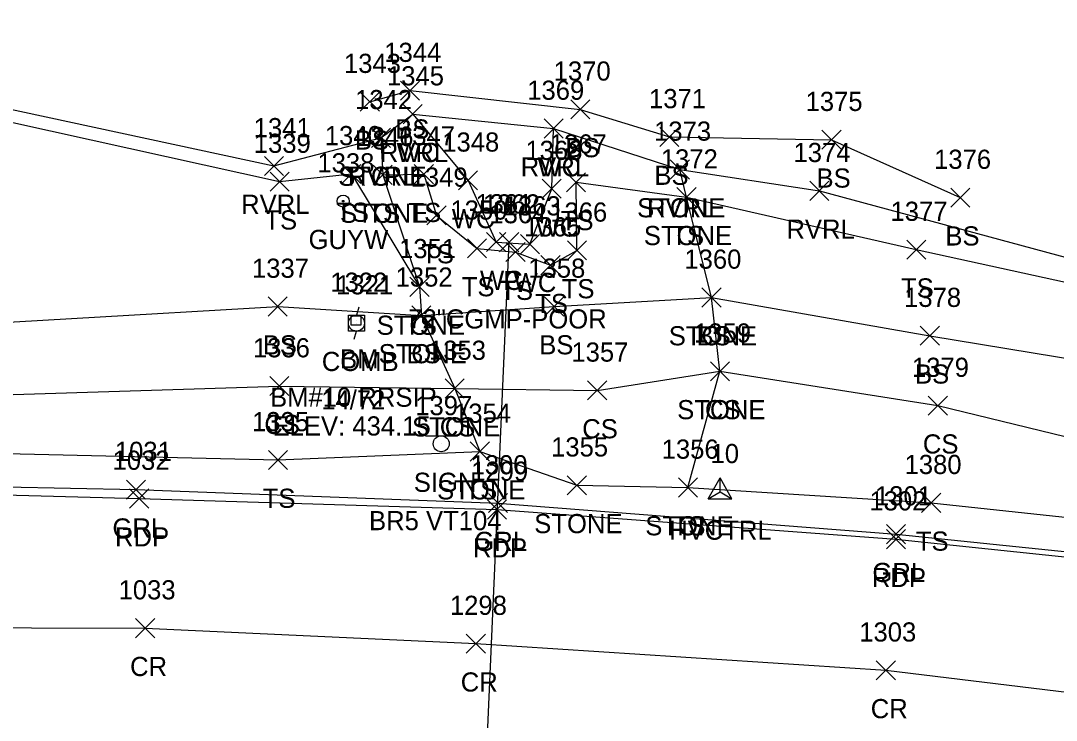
# Model space of a CAD drawing. Extents: x 1514253 to 1516033, y 782541 to 785002.
# Drawn here: x 1515259.8 to 1515367.9, y 782689.3 to 782762.3 of the extents above; entities that cross this region are included whole.
import ezdxf

# ---------------------------------------------------------------- set-up
doc = ezdxf.new("R2010")
doc.units = 0
for name, color, linetype in [('C_A', 7, 'Continuous'), ('C_C', 7, 'Continuous'), ('C_I', 7, 'Continuous'), ('CPBM', 7, 'Continuous'), ('CPSM', 7, 'Continuous'), ('D_A', 7, 'Continuous'), ('D_C', 7, 'Continuous'), ('D_I', 7, 'Continuous'), ('D_TIC', 7, 'Continuous'), ('DCP', 7, 'Continuous'), ('L_A', 7, 'Continuous'), ('L_I', 7, 'Continuous'), ('L_TIC', 7, 'Continuous'), ('LASF', 7, 'Continuous'), ('LAWE', 7, 'Continuous'), ('LELB', 7, 'Continuous'), ('P_A', 7, 'Continuous'), ('P_I', 7, 'Continuous'), ('P_TIC', 7, 'Continuous'), ('PET', 7, 'Continuous'), ('PRC', 7, 'Continuous'), ('R_A', 7, 'Continuous'), ('R_I', 7, 'Continuous'), ('R_TIC', 7, 'Continuous'), ('RGR', 7, 'Continuous'), ('S_A', 7, 'Continuous'), ('S_C', 7, 'Continuous'), ('S_I', 7, 'Continuous'), ('SSGN', 7, 'Continuous'), ('U_A', 7, 'Continuous'), ('U_C', 7, 'Continuous'), ('U_I', 7, 'Continuous'), ('UP', 7, 'Continuous'), ('UPGW', 7, 'Continuous')]:
    doc.layers.add(name, color=color, linetype=linetype)

msp = doc.modelspace()

# ---------------------------------------------------------------- linework, layer by layer
at = {"layer": 'CPBM'}
for p, q in [((1515294.35, 782730.48), (1515294.35, 782731.48)), ((1515294.35, 782731.48), (1515295.35, 782731.48)), ((1515295.35, 782731.48), (1515295.35, 782730.48)), ((1515295.35, 782730.48), (1515294.35, 782730.48)), ((1515294.85, 782730.98), (1515294.85, 782730.98)), ((1515294.85, 782730.98), (1515294.85, 782730.98))]:
    msp.add_line(p, q, dxfattribs=at)
at = {"layer": 'CPSM'}
for p, q in [((1515331.58, 782712.38), (1515332.83, 782714.55)), ((1515334.08, 782712.38), (1515332.83, 782714.55)), ((1515332.83, 782713.1), (1515332.83, 782714.55)), ((1515331.58, 782712.38), (1515332.83, 782713.1)), ((1515332.83, 782713.1), (1515332.83, 782713.1)), ((1515332.83, 782713.1), (1515334.08, 782712.38)), ((1515331.58, 782712.38), (1515334.08, 782712.38))]:
    msp.add_line(p, q, dxfattribs=at)
at = {"layer": 'D_TIC'}
for points in [[(1515309.82, 782738.15), (1515311.82, 782740.15)], [(1515311.82, 782738.15), (1515309.82, 782740.15)]]:
    msp.add_lwpolyline(points, dxfattribs=at)
at = {"layer": 'DCP'}
msp.add_lwpolyline([(1515307.3, 782659.25), (1515310.82, 782739.15)], dxfattribs=at)
at = {"layer": 'L_TIC'}
for points in [[(1515299.48, 782753.97), (1515301.48, 782755.97)], [(1515301.48, 782753.97), (1515299.48, 782755.97)], [(1515295.28, 782752.82), (1515297.28, 782754.82)], [(1515297.28, 782752.82), (1515295.28, 782754.82)], [(1515299.76, 782751.52), (1515301.76, 782753.52)], [(1515301.76, 782751.52), (1515299.76, 782753.52)], [(1515299.76, 782751.52), (1515301.76, 782753.52)], [(1515301.76, 782751.52), (1515299.76, 782753.52)], [(1515317.25, 782752.02), (1515319.25, 782754.02)], [(1515319.25, 782752.02), (1515317.25, 782754.02)], [(1515314.46, 782750.02), (1515316.46, 782752.02)], [(1515316.46, 782750.02), (1515314.46, 782752.02)], [(1515314.46, 782750.02), (1515316.46, 782752.02)], [(1515316.46, 782750.02), (1515314.46, 782752.02)], [(1515296.44, 782749.04), (1515298.44, 782751.04)], [(1515298.44, 782749.04), (1515296.44, 782751.04)], [(1515296.44, 782749.04), (1515298.44, 782751.04)], [(1515298.44, 782749.04), (1515296.44, 782751.04)], [(1515326.54, 782749.14), (1515328.54, 782751.14)], [(1515328.54, 782749.14), (1515326.54, 782751.14)], [(1515343.46, 782748.85), (1515345.46, 782750.85)], [(1515345.46, 782748.85), (1515343.46, 782750.85)], [(1515285.28, 782746.11), (1515287.28, 782748.11)], [(1515287.28, 782746.11), (1515285.28, 782748.11)], [(1515327.64, 782745.75), (1515329.64, 782747.75)], [(1515329.64, 782745.75), (1515327.64, 782747.75)], [(1515327.64, 782745.75), (1515329.64, 782747.75)], [(1515329.64, 782745.75), (1515327.64, 782747.75)], [(1515293.36, 782745.28), (1515295.36, 782747.28)], [(1515295.36, 782745.28), (1515293.36, 782747.28)], [(1515296.63, 782745.18), (1515298.63, 782747.18)], [(1515298.63, 782745.18), (1515296.63, 782747.18)], [(1515296.63, 782745.18), (1515298.63, 782747.18)], [(1515298.63, 782745.18), (1515296.63, 782747.18)], [(1515300.91, 782745.26), (1515302.91, 782747.26)], [(1515302.91, 782745.26), (1515300.91, 782747.26)], [(1515305.53, 782744.61), (1515307.53, 782746.61)], [(1515307.53, 782744.61), (1515305.53, 782746.61)], [(1515285.87, 782744.48), (1515287.87, 782746.48)], [(1515287.87, 782744.48), (1515285.87, 782746.48)], [(1515314.26, 782743.74), (1515316.26, 782745.74)], [(1515316.26, 782743.74), (1515314.26, 782745.74)], [(1515316.8, 782744.41), (1515318.8, 782746.41)], [(1515318.8, 782744.41), (1515316.8, 782746.41)], [(1515342.2, 782743.52), (1515344.2, 782745.52)], [(1515344.2, 782743.52), (1515342.2, 782745.52)], [(1515328.34, 782742.85), (1515330.34, 782744.85)], [(1515330.34, 782742.85), (1515328.34, 782744.85)], [(1515328.34, 782742.85), (1515330.34, 782744.85)], [(1515330.34, 782742.85), (1515328.34, 782744.85)], [(1515356.91, 782742.81), (1515358.91, 782744.81)], [(1515358.91, 782742.81), (1515356.91, 782744.81)], [(1515302.24, 782740.95), (1515304.24, 782742.95)], [(1515304.24, 782740.95), (1515302.24, 782742.95)], [(1515308.47, 782738.17), (1515310.47, 782740.17)], [(1515310.47, 782738.17), (1515308.47, 782740.17)], [(1515306.47, 782737.51), (1515308.47, 782739.51)], [(1515308.47, 782737.51), (1515306.47, 782739.51)], [(1515310.49, 782737.13), (1515312.49, 782739.13)], [(1515312.49, 782737.13), (1515310.49, 782739.13)], [(1515311.99, 782737.95), (1515313.99, 782739.95)], [(1515313.99, 782737.95), (1515311.99, 782739.95)], [(1515316.9, 782737.3), (1515318.9, 782739.3)], [(1515318.9, 782737.3), (1515316.9, 782739.3)], [(1515352.31, 782737.38), (1515354.31, 782739.38)], [(1515354.31, 782737.38), (1515352.31, 782739.38)], [(1515314.13, 782735.76), (1515316.13, 782737.76)], [(1515316.13, 782735.76), (1515314.13, 782737.76)], [(1515300.46, 782733.49), (1515302.46, 782735.49)], [(1515302.46, 782733.49), (1515300.46, 782735.49)], [(1515300.46, 782733.49), (1515302.46, 782735.49)], [(1515302.46, 782733.49), (1515300.46, 782735.49)], [(1515330.94, 782732.39), (1515332.94, 782734.39)], [(1515332.94, 782732.39), (1515330.94, 782734.39)], [(1515330.94, 782732.39), (1515332.94, 782734.39)], [(1515332.94, 782732.39), (1515330.94, 782734.39)], [(1515285.67, 782731.44), (1515287.67, 782733.44)], [(1515287.67, 782731.44), (1515285.67, 782733.44)], [(1515300.66, 782730.52), (1515302.66, 782732.52)], [(1515302.66, 782730.52), (1515300.66, 782732.52)], [(1515300.66, 782730.52), (1515302.66, 782732.52)], [(1515302.66, 782730.52), (1515300.66, 782732.52)], [(1515314.52, 782731.45), (1515316.52, 782733.45)], [(1515316.52, 782731.45), (1515314.52, 782733.45)], [(1515353.73, 782728.4), (1515355.73, 782730.4)], [(1515355.73, 782728.4), (1515353.73, 782730.4)], [(1515331.82, 782724.68), (1515333.82, 782726.68)], [(1515333.82, 782724.68), (1515331.82, 782726.68)], [(1515331.82, 782724.68), (1515333.82, 782726.68)], [(1515333.82, 782724.68), (1515331.82, 782726.68)], [(1515285.83, 782723.14), (1515287.83, 782725.14)], [(1515287.83, 782723.14), (1515285.83, 782725.14)], [(1515304.14, 782722.88), (1515306.14, 782724.88)], [(1515306.14, 782722.88), (1515304.14, 782724.88)], [(1515304.14, 782722.88), (1515306.14, 782724.88)], [(1515306.14, 782722.88), (1515304.14, 782724.88)], [(1515319.01, 782722.69), (1515321.01, 782724.69)], [(1515321.01, 782722.69), (1515319.01, 782724.69)], [(1515354.56, 782721.1), (1515356.56, 782723.1)], [(1515356.56, 782721.1), (1515354.56, 782723.1)], [(1515285.69, 782715.43), (1515287.69, 782717.43)], [(1515287.69, 782715.43), (1515285.69, 782717.43)], [(1515306.76, 782716.31), (1515308.76, 782718.31)], [(1515308.76, 782716.31), (1515306.76, 782718.31)], [(1515306.76, 782716.31), (1515308.76, 782718.31)], [(1515308.76, 782716.31), (1515306.76, 782718.31)], [(1515316.89, 782712.79), (1515318.89, 782714.79)], [(1515318.89, 782712.79), (1515316.89, 782714.79)], [(1515328.48, 782712.56), (1515330.48, 782714.56)], [(1515330.48, 782712.56), (1515328.48, 782714.56)], [(1515328.48, 782712.56), (1515330.48, 782714.56)], [(1515330.48, 782712.56), (1515328.48, 782714.56)], [(1515353.86, 782710.96), (1515355.86, 782712.96)], [(1515355.86, 782710.96), (1515353.86, 782712.96)]]:
    msp.add_lwpolyline(points, dxfattribs=at)
at = {"layer": 'LASF'}
msp.add_lwpolyline([(1515297.44, 782750.04), (1515297.63, 782746.18), (1515301.46, 782734.49), (1515301.66, 782731.52), (1515305.14, 782723.88), (1515307.76, 782717.31), (1515317.89, 782713.79), (1515329.48, 782713.56), (1515332.82, 782725.68), (1515331.94, 782733.39), (1515329.34, 782743.85), (1515328.64, 782746.75)], dxfattribs=at)
at = {"layer": 'LAWE'}
for points in [[(1515202.17, 782762.27), (1515243.71, 782756.27), (1515286.28, 782747.11), (1515297.44, 782750.04), (1515300.76, 782752.52), (1515315.46, 782751.02), (1515328.64, 782746.75), (1515343.2, 782744.52), (1515396.17, 782730.21), (1515410.48, 782726.67), (1515425.65, 782730.86), (1515462.57, 782730.18)], [(1515300.76, 782752.52), (1515306.53, 782745.61), (1515309.47, 782739.17), (1515312.99, 782738.95), (1515315.26, 782744.74), (1515315.46, 782751.02)]]:
    msp.add_lwpolyline(points, dxfattribs=at)
at = {"layer": 'LELB'}
for points in [[(1515202.79, 782759.81), (1515243.26, 782755.13), (1515286.87, 782745.48), (1515294.36, 782746.28), (1515301.46, 782734.49)], [(1515296.28, 782753.82), (1515300.48, 782754.97), (1515318.25, 782753.02), (1515327.54, 782750.14), (1515344.46, 782749.85), (1515357.91, 782743.81)], [(1515297.63, 782746.18), (1515301.91, 782746.26), (1515303.24, 782741.95), (1515307.47, 782738.51), (1515311.49, 782738.13), (1515315.13, 782736.76), (1515317.9, 782738.3), (1515317.8, 782745.41), (1515329.34, 782743.85), (1515353.31, 782738.38), (1515396.39, 782728.96), (1515412.77, 782722.27), (1515425.22, 782714.96)], [(1515201.95, 782733.37), (1515243.57, 782729.95), (1515286.67, 782732.44), (1515301.66, 782731.52), (1515315.52, 782732.45), (1515331.94, 782733.39), (1515354.73, 782729.4), (1515394.7, 782722.81), (1515412.77, 782722.27)], [(1515200.97, 782724.68), (1515243.49, 782722.77), (1515286.83, 782724.14), (1515305.14, 782723.88), (1515320.01, 782723.69), (1515332.82, 782725.68), (1515355.56, 782722.1), (1515394.29, 782712.68), (1515425.22, 782714.96), (1515459.54, 782709.6)], [(1515200.03, 782717.69), (1515243.31, 782717.45), (1515286.69, 782716.43), (1515307.76, 782717.31)], [(1515329.48, 782713.56), (1515354.86, 782711.96), (1515389.93, 782708.21), (1515422.77, 782703.93), (1515456.54, 782698.83)]]:
    msp.add_lwpolyline(points, dxfattribs=at)
at = {"layer": 'P_TIC'}
for points in [[(1515271.2, 782711.4), (1515273.2, 782713.4)], [(1515273.2, 782711.4), (1515271.2, 782713.4)], [(1515308.56, 782710.26), (1515310.56, 782712.26)], [(1515310.56, 782710.26), (1515308.56, 782712.26)], [(1515350.19, 782707.16), (1515352.19, 782709.16)], [(1515352.19, 782707.16), (1515350.19, 782709.16)], [(1515271.83, 782697.88), (1515273.83, 782699.88)], [(1515273.83, 782697.88), (1515271.83, 782699.88)], [(1515306.34, 782696.26), (1515308.34, 782698.26)], [(1515308.34, 782696.26), (1515306.34, 782698.26)], [(1515349.13, 782693.48), (1515351.13, 782695.48)], [(1515351.13, 782693.48), (1515349.13, 782695.48)]]:
    msp.add_lwpolyline(points, dxfattribs=at)
at = {"layer": 'PET'}
msp.add_lwpolyline([(1515198.6, 782712.94), (1515237.64, 782713.34), (1515272.2, 782712.4), (1515309.56, 782711.26), (1515351.19, 782708.16), (1515392.07, 782703.88), (1515423.17, 782699.74), (1515455.77, 782695.06)], dxfattribs=at)
at = {"layer": 'PRC'}
msp.add_lwpolyline([(1515198.29, 782698.44), (1515237.18, 782698.99), (1515272.83, 782698.88), (1515307.34, 782697.26), (1515350.13, 782694.48), (1515391.03, 782689.51), (1515420.87, 782685.75), (1515453.49, 782680.58)], dxfattribs=at)
at = {"layer": 'R_TIC'}
for points in [[(1515270.88, 782712.33), (1515272.88, 782714.33)], [(1515272.88, 782712.33), (1515270.88, 782714.33)], [(1515308.65, 782710.93), (1515310.65, 782712.93)], [(1515310.65, 782710.93), (1515308.65, 782712.93)], [(1515350.2, 782707.69), (1515352.2, 782709.69)], [(1515352.2, 782707.69), (1515350.2, 782709.69)]]:
    msp.add_lwpolyline(points, dxfattribs=at)
at = {"layer": 'RGR'}
msp.add_lwpolyline([(1515198.57, 782713.8), (1515237.6, 782714.04), (1515271.88, 782713.33), (1515309.65, 782711.93), (1515351.2, 782708.69), (1515392.07, 782704.46), (1515423.15, 782700.51), (1515456.3, 782695.76)], dxfattribs=at)
at = {"layer": 'SSGN'}
for p, q in [((1515302.08, 782718.95), (1515305.42, 782718.95)), ((1515303.73, 782718.12), (1515303.73, 782718.12))]:
    msp.add_line(p, q, dxfattribs=at)
msp.add_circle((1515303.73, 782718.12), 0.833, dxfattribs=at)
at = {"layer": 'UP'}
for p, q in [((1515294.05, 782729.88), (1515294.05, 782731.55)), ((1515294.05, 782731.55), (1515295.72, 782731.55)), ((1515295.13, 782732.38), (1515294.88, 782731.55)), ((1515295.72, 782731.55), (1515295.72, 782729.88)), ((1515294.88, 782730.71), (1515294.88, 782730.71)), ((1515295.72, 782729.88), (1515294.05, 782729.88)), ((1515294.63, 782729.05), (1515294.88, 782729.88))]:
    msp.add_line(p, q, dxfattribs=at)
msp.add_circle((1515294.88, 782730.71), 0.833, dxfattribs=at)
at = {"layer": 'UPGW'}
for radius in [0.625, 0.0833]:
    msp.add_circle((1515293.5, 782743.44), radius, dxfattribs=at)

# ---------------------------------------------------------------- texts
at = {"layer": 'C_A'}
for s, p in [('BM', (1515293.17, 782725.98)), ('HVCTRL', (1515327.52, 782708.1))]:
    msp.add_text(s, height=2, dxfattribs=at).set_placement(p)
at = {"layer": 'C_C'}
for s, p in [('BM#10 RRSIP', (1515285.87, 782721.98)), ('ELEV: 434.15', (1515286.13, 782718.98))]:
    msp.add_text(s, height=2, dxfattribs=at).set_placement(p)
at = {"layer": 'C_I'}
for s, p in [('1322', (1515292.16, 782733.98)), ('10', (1515331.84, 782716.1))]:
    msp.add_text(s, height=2, dxfattribs=at).set_placement(p)
at = {"layer": 'D_A'}
msp.add_text('P', height=2, dxfattribs=at).set_placement((1515310.2, 782734.15))
at = {"layer": 'D_C'}
msp.add_text('72"CGMP-POOR', height=2, dxfattribs=at).set_placement((1515300.29, 782730.15))
at = {"layer": 'D_I'}
msp.add_text('1362', height=2, dxfattribs=at).set_placement((1515308.08, 782742.15))
at = {"layer": 'L_A'}
for s, p in [('BS', (1515298.93, 782749.97)), ('BS', (1515294.72, 782748.82)), ('BS', (1515316.69, 782748.02)), ('RVRL', (1515297.33, 782747.52)), ('WC', (1515299.07, 782747.52)), ('RVRL', (1515312.03, 782746.02)), ('WC', (1515313.77, 782746.02)), ('STONE', (1515292.98, 782745.04)), ('RVRL', (1515294, 782745.04)), ('BS', (1515325.98, 782745.14)), ('BS', (1515342.9, 782744.85)), ('RVRL', (1515282.85, 782742.11)), ('STONE', (1515324.18, 782741.75)), ('RVRL', (1515325.21, 782741.75)), ('TS', (1515285.28, 782740.48)), ('TS', (1515292.77, 782741.28)), ('STONE', (1515293.17, 782741.18)), ('TS', (1515296.03, 782741.18)), ('TS', (1515300.32, 782741.26)), ('WC', (1515304.84, 782740.61)), ('TS', (1515316.21, 782740.41)), ('WC', (1515313.57, 782739.74)), ('RVRL', (1515339.76, 782739.52)), ('STONE', (1515324.88, 782738.85)), ('TS', (1515327.75, 782738.85)), ('BS', (1515356.35, 782738.81)), ('TS', (1515301.65, 782736.95)), ('WC', (1515307.78, 782734.17)), ('WC', (1515311.29, 782733.95)), ('TS', (1515305.88, 782733.51)), ('TS', (1515309.9, 782733.13)), ('TS', (1515316.31, 782733.3)), ('TS', (1515351.72, 782733.38)), ('TS', (1515313.54, 782731.76)), ('STONE', (1515297, 782729.49)), ('TS', (1515299.87, 782729.49)), ('STONE', (1515327.48, 782728.39)), ('BS', (1515330.38, 782728.39)), ('BS', (1515285.11, 782727.44)), ('BS', (1515313.96, 782727.45)), ('STONE', (1515297.2, 782726.52)), ('BS', (1515300.1, 782726.52)), ('BS', (1515353.18, 782724.4)), ('STONE', (1515328.36, 782720.68)), ('CS', (1515331.26, 782720.68)), ('CS', (1515285.27, 782719.14)), ('STONE', (1515300.69, 782718.88)), ('CS', (1515303.58, 782718.88)), ('CS', (1515318.45, 782718.69)), ('CS', (1515354, 782717.1)), ('STONE', (1515303.3, 782712.31)), ('TS', (1515306.17, 782712.31)), ('TS', (1515285.1, 782711.43)), ('STONE', (1515313.44, 782708.79)), ('STONE', (1515325.03, 782708.56)), ('TS', (1515327.89, 782708.56)), ('TS', (1515353.27, 782706.96))]:
    msp.add_text(s, height=2, dxfattribs=at).set_placement(p)
at = {"layer": 'L_I'}
for s, p in [('1344', (1515297.79, 782757.97)), ('1343', (1515293.58, 782756.82)), ('1345', (1515298.07, 782755.52)), ('1345', (1515298.07, 782755.52)), ('1370', (1515315.47, 782756.02)), ('1369', (1515312.71, 782754.02)), ('1369', (1515312.71, 782754.02)), ('1342', (1515294.74, 782753.04)), ('1342', (1515294.74, 782753.04)), ('1371', (1515325.42, 782753.14)), ('1375', (1515341.76, 782752.85)), ('1341', (1515284.16, 782750.11)), ('1340', (1515291.58, 782749.28)), ('1346', (1515294.88, 782749.18)), ('1346', (1515294.88, 782749.18)), ('1347', (1515299.22, 782749.26)), ('1373', (1515325.95, 782749.75)), ('1373', (1515325.95, 782749.75)), ('1339', (1515284.17, 782748.48)), ('1348', (1515303.84, 782748.61)), ('1367', (1515315.06, 782748.41)), ('1368', (1515312.52, 782747.74)), ('1372', (1515326.65, 782746.85)), ('1372', (1515326.65, 782746.85)), ('1374', (1515340.5, 782747.52)), ('1376', (1515355.17, 782746.81)), ('1349', (1515300.54, 782744.95)), ('1350', (1515304.69, 782741.51)), ('1361', (1515307.3, 782742.17)), ('1363', (1515310.25, 782741.95)), ('1366', (1515315.11, 782741.3)), ('1377', (1515350.62, 782741.38)), ('1364', (1515308.75, 782741.13)), ('1365', (1515312.39, 782739.76)), ('1351', (1515299.33, 782737.49)), ('1351', (1515299.33, 782737.49)), ('1360', (1515329.11, 782736.39)), ('1360', (1515329.11, 782736.39)), ('1337', (1515283.98, 782735.44)), ('1358', (1515312.82, 782735.45)), ('1352', (1515298.97, 782734.52)), ('1352', (1515298.97, 782734.52)), ('1378', (1515352.04, 782732.4)), ('1359', (1515330.12, 782728.68)), ('1359', (1515330.12, 782728.68)), ('1336', (1515284.08, 782727.14)), ('1353', (1515302.45, 782726.88)), ('1353', (1515302.45, 782726.88)), ('1357', (1515317.32, 782726.69)), ('1379', (1515352.86, 782725.1)), ('1354', (1515305.07, 782720.31)), ('1354', (1515305.07, 782720.31)), ('1335', (1515283.99, 782719.43)), ('1355', (1515315.2, 782716.79)), ('1356', (1515326.74, 782716.56)), ('1356', (1515326.74, 782716.56)), ('1380', (1515352.09, 782714.96))]:
    msp.add_text(s, height=2, dxfattribs=at).set_placement(p)
at = {"layer": 'P_A'}
for s, p in [('RDP', (1515269.69, 782707.4)), ('RDP', (1515307.05, 782706.26)), ('RDP', (1515348.68, 782703.16)), ('CR', (1515271.26, 782693.88)), ('CR', (1515305.77, 782692.26)), ('CR', (1515348.56, 782689.48))]:
    msp.add_text(s, height=2, dxfattribs=at).set_placement(p)
at = {"layer": 'P_I'}
for s, p in [('1032', (1515269.43, 782715.4)), ('1299', (1515306.86, 782714.26)), ('1302', (1515348.42, 782711.16)), ('1033', (1515270.06, 782701.88)), ('1298', (1515304.64, 782700.26)), ('1303', (1515347.36, 782697.48))]:
    msp.add_text(s, height=2, dxfattribs=at).set_placement(p)
at = {"layer": 'R_A'}
for p in [(1515269.42, 782708.33), (1515307.19, 782706.93), (1515348.74, 782703.69)]:
    msp.add_text('GRL', height=2, dxfattribs=at).set_placement(p)
at = {"layer": 'R_I'}
for s, p in [('1031', (1515269.67, 782716.33)), ('1300', (1515306.79, 782714.93)), ('1301', (1515349, 782711.69))]:
    msp.add_text(s, height=2, dxfattribs=at).set_placement(p)
at = {"layer": 'S_A'}
msp.add_text('SIGN', height=2, dxfattribs=at).set_placement((1515300.87, 782713.1))
at = {"layer": 'S_C'}
msp.add_text('BR5 VT104', height=2, dxfattribs=at).set_placement((1515296.2, 782709.1))
at = {"layer": 'S_I'}
msp.add_text('1397', height=2, dxfattribs=at).set_placement((1515301.02, 782721.1))
at = {"layer": 'U_A'}
for s, p in [('GUYW', (1515289.89, 782738.44)), ('COMB', (1515291.27, 782725.71))]:
    msp.add_text(s, height=2, dxfattribs=at).set_placement(p)
at = {"layer": 'U_C'}
msp.add_text('14/72', height=2, dxfattribs=at).set_placement((1515291.21, 782721.71))
at = {"layer": 'U_I'}
for s, p in [('1338', (1515290.81, 782746.44)), ('1321', (1515292.76, 782733.71))]:
    msp.add_text(s, height=2, dxfattribs=at).set_placement(p)

doc.saveas('drawing.dxf')
